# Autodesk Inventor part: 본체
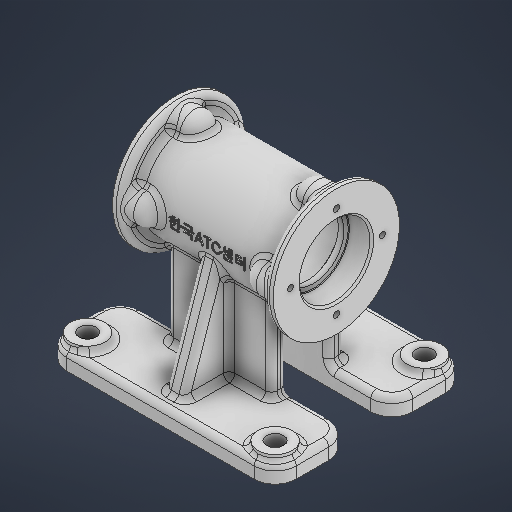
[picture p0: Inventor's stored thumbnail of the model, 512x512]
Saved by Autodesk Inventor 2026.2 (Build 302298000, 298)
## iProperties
Created: 2026-06
Part Number: 본체
Material: 일반
Document SubType Name: Modeling
Designer: sec7
Density: 1 g/cm^3
Appearance: 기본값
Author: sec7
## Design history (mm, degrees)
sketch "스케치1"
  geometry: C1 r 25 at (0, 0); 1 further point
  constraints: 1 centre point, 1 coincident
  dimensions: "d0" = 50 diameter of C1
extrude "돌출1" new body sketch "스케치1" stored distance "d1" = 84; taper "d2" = 0 deg
sketch "스케치2"
  geometry: C1 r 33 at (0, 0); 1 further point
  constraints: 1 centre point, 1 coincident
  dimensions: "d3" = 66 diameter of C1
extrude "돌출2" join sketch "스케치2" distance "d4" = 5; taper "d5" = 0 deg
sketch "스케치3"
  geometry: C1 r 8 at (0, 24); 1 further point
  constraints: 1 centre point, 1 vertical alignment
  dimensions: "d6" = 16 diameter of C1; "d7" = 24 distance of point (0, 0) C1.centre
extrude "돌출3" join sketch "스케치3" distance "d8" = 13; taper "d9" = 0 deg
fillet "모깎기1" dims "d10" = 8
sketch "스케치4"
  geometry: 2 further points
  constraints: 1 vertical alignment
  dimensions: "d11" = 24 distance of point (0, 0) point (0, 24)
hole "구멍1" sketch "스케치4" at (0, 24) diameter "d12" = 3.242; stored, may be unused: countersink angle "d16" = 90 deg, drill point angle "d18" = 120 deg; dims "d13" = 8, "d14" = 4, "d15" = 2, "d17" = 10
node "작업 평면1"
sketch "스케치5"
  geometry: L1 (60, 11)-(-60, 11); L2 (-60, 11)-(-60, 50); L3 (-60, 50)-(60, 50); L4 (60, 50)-(60, 11); L5 (60, -50)-(-60, -50); L6 (-60, -50)-(-60, -11); L7 (-60, -11)-(60, -11); L8 (60, -11)-(60, -50); 3 further points
  constraints: 16 end point, 4 parallel, 2 horizontal, 2 midpoint, 2 perpendicular, 2 vertical alignment, 1 collinear
  dimensions: "d23" = 39 distance of L7.end L5.start; "d24" = 120 distance of L5.start L5.end; "d25" = 120 distance of L1.start L1.end; "d26" = 50 distance from line of point (0, 0) L5; "d27" = 100 distance between parallel lines of L3 L5
extrude "돌출4" join sketch "스케치5" distance "d28" = 9; taper "d29" = 0 deg
sketch "스케치6"
  geometry: L1 (60, -11)-(-60, -11) reference; L2 (-27, -11)-(27, -11); L3 (27, -11)-(27, -19); L4 (27, -19)-(-27, -19); L5 (-27, -19)-(-27, -11); L6 (-60, 11)-(60, 11) reference; L7 (-27, 11)-(27, 11); L8 (27, 11)-(27, 19); L9 (27, 19)-(-27, 19); L10 (-27, 19)-(-27, 11); 5 further points
  constraints: 16 end point, 4 parallel, 2 horizontal, 2 midpoint, 2 perpendicular, 2 point on line, 2 vertical alignment
  dimensions: "d30" = 54 distance of L3.end L4.end; "d31" = 8 distance of L2.end L3.end; "d32" = 54 distance of L8.end L9.end; "d33" = 8 distance of L9.end L7.start
extrude "돌출5" join sketch "스케치6" stored distance "d8" = 13; stored distance "d34" = 9; taper "d35" = 0 deg; dims "d16" = 90 deg
sketch "스케치7"
  geometry: L1 (-61, 11)-(-61, 50) reference; L2 (-61, 43)-(-6.346, 24.181); L3 (-61, 19)-(-16.248, 19) reference; A1 r 25 centre (0, 0) between (-6.346, 24.181) and (-16.248, 19) reference; 1 further point
  constraints: 2 end point, 1 point on circle, 1 point on line
  dimensions: "d36" = 7 distance of L1.end L2.start; "d37" = 19 deg angle of L3 L2
feature "리브1" sketch "스케치7" dims "d38" = 1, "d39" = 10, "d40" = 0, "d41" = 0, "d42" = 1, "d43" = 1
fillet "모깎기4" dims "d46" = 3
fillet "모깎기5" dims "d47" = 3
sketch "스케치8"
  geometry: C1 r 9 at (-49, -39); C2 r 9 at (49, -39); C3 r 9 at (-49, 39); C4 r 9 at (49, 39); 1 further point
  constraints: 4 centre point, 2 horizontal alignment, 2 vertical alignment
  dimensions: "d51" = 18 diameter of C1; "d52" = 18 diameter of C2; "d53" = 18 diameter of C3; "d54" = 18 diameter of C4; "d55" = 78 distance of C1.centre C3.centre; "d56" = 39 vertical distance of point (0, 0) C3.centre; "d57" = 98 distance of C4.centre C3.centre; "d58" = 49 horizontal distance of point (0, 0) C3.centre
extrude "돌출6" join sketch "스케치8" distance "d59" = 3; taper "d60" = 0 deg
fillet "모깎기7" dims "d49" = 3
fillet "모깎기8" dims "d50" = 3
fillet "모깎기9" dims "d61" = 11
sketch "스케치9"
  geometry: L1 (-42, 0)-(42, 0); L2 (42, -33)-(42, 33) reference; L3 (-42, 25)-(-42, -25) reference; L4 (-42, 18.5)-(-30.3, 18.5); L5 (-30, 18.2)-(-30, 16); L6 (-30, 16)-(-27, 16); L7 (-27, 16)-(-27, 17); L8 (-24, 20)-(24, 20); L9 (27, 17)-(27, 16); L10 (27, 16)-(30, 16); L11 (30, 16)-(30, 18.2); L12 (30.3, 18.5)-(42, 18.5); A1 r 0.3 centre (-30.3, 18.2) between (-30, 18.2) and (-30.3, 18.5); A2 r 0.3 centre (30.3, 18.2) between (30.3, 18.5) and (30, 18.2); A3 r 3 centre (24, 17) between (27, 17) and (24, 20); A4 r 3 centre (-24, 17) between (-24, 20) and (-27, 17); 3 further points
  constraints: 20 end point, 10 point on line, 8 point on circle, 8 tangent, 6 perpendicular, 4 centre point, 2 equal radius, 2 midpoint, 1 horizontal
  dimensions: "d63" = 40 diameter of L8 L1; "d64" = 37 diameter of L12 L1; "d65" = 32 diameter of L6 L1; "d66" = 12 distance of L4.start point (-30, 18.5); "d67" = 54 distance between parallel lines of L9 L7; "d68" = 27 distance from line of point (0, 0) L7; "d69" = 12 distance of point (30, 18.5) L12.end; "d70" = 0.3 radius of A1; "d71" = 3 radius of A3
revolve "회전1" sketch "스케치9" stored, may be unused: angle "d72" = 90 deg
fillet "모깎기11" dims "d73" = 3
fillet "모깎기13" dims "d75" = 3
fillet "모깎기14" dims "d76" = 3
chamfer "모따기1" distance "d77" = 1; stored, may be unused: second distance "d78" = 2, angle "d79" = 45 deg
sketch "스케치10"
  geometry: C1 r 9 at (0, 0) reference; C2 r 9 at (98, 0) reference; C3 r 9 at (0, -78) reference; C4 r 9 at (98, -78) reference; 5 further points
  constraints: 4 coincident
hole "구멍2" sketch "스케치10" at (0, 0), (98, 0), (0, -78), (98, -78) diameter "d80" = 9; stored, may be unused: countersink angle "d84" = 90 deg, drill point angle "d86" = 120 deg; dims "d81" = 8, "d82" = 4, "d83" = 2, "d85" = 10
fillet "모깎기15" dims "d87" = 3
sketch "스케치11" dims "d0" = 50
  geometry: L1 (0, 0)-(98, 0) reference; 3 further points
  constraints: 1 midpoint, 1 vertical alignment, 1 other
  dimensions: "d88" = 70 distance from line of L1 point (49, 70)
fillet "모깎기16" dims "d89" = 3
feature "엠보싱1" dims "d0" = 50, "d90" = 0.5, "d91" = 0
sketch "스케치12"
  geometry: L1 (-58, -11)-(-26.833, -11) reference; L2 (-26.833, 11)-(-58, 11) reference; L3 (-50, 11)-(-50, -11); L4 (-70, -22)-(-70, -11) reference; 1 further point
  constraints: 2 end point, 2 point on line, 1 perpendicular
  dimensions: "d92" = 20 distance between parallel lines of L4 L3
feature "리브2" sketch "스케치12" dims "d93" = 1, "d94" = 10, "d95" = 0, "d96" = 0, "d97" = 1, "d98" = 1
fillet "모깎기17" dims "d99" = 3
fillet "모깎기18" dims "d100" = 3
node "솔리드1"
pattern_circular "원형 패턴1" dims "d20" = 360 deg
mirror "미러1"
mirror "미러2"
feature "A9D066F2-1C7D-4E18-AEED-F7BC21143FA4" dims "d80" = 9, "d81" = 8, "d82" = 4, "d83" = 2, "d84" = 90 deg, "d85" = 10, "d86" = 120 deg
